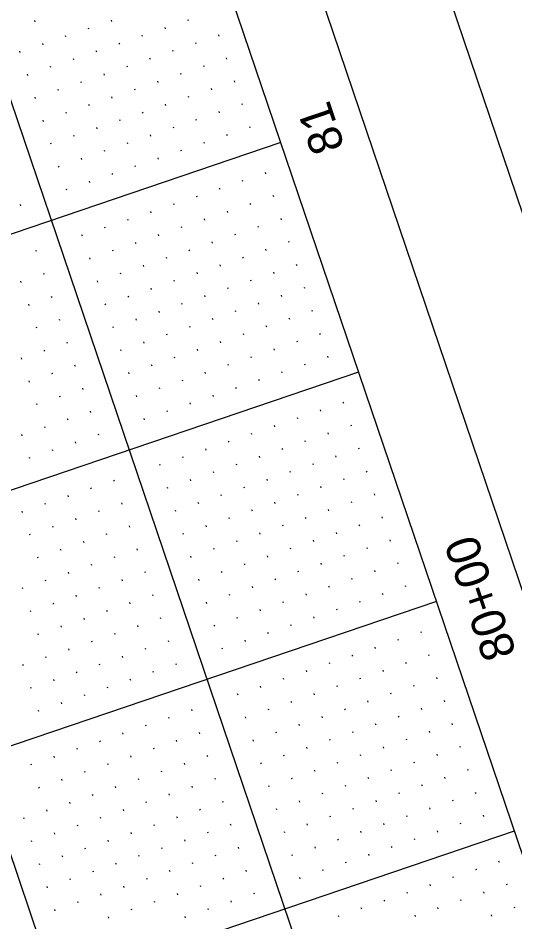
# Model space of a CAD drawing. Extents: x 2150800 to 2152547, y 141860 to 143950.
# Drawn here: x 2152038.2 to 2152140.8, y 143015.3 to 143201.8 of the extents above; entities that cross this region are included whole.
import ezdxf

# ---------------------------------------------------------------- set-up
doc = ezdxf.new("R2010")
doc.units = 0
for name, color, linetype in [('SHT_Plan_Profile_Sheet_Sta_Txt', 7, 'Continuous'), ('SHT_Plot_Shape_Half', 7, 'Continuous'), ('SHT_Profile_Grid_Major', 7, 'Continuous'), ('SHT_Profile_Grid_Minor', 7, 'Continuous'), ('SHT_Sheet_Border', 7, 'Continuous')]:
    doc.layers.add(name, color=color, linetype=linetype)

msp = doc.modelspace()

# ---------------------------------------------------------------- linework, layer by layer
at = {"layer": 'SHT_Plot_Shape_Half'}
msp.add_lwpolyline([(2151391.39, 141950.92), (2150845.24, 143560.8), (2151886.93, 143914.19), (2152433.08, 142304.31)], close=True, dxfattribs=at)
at = {"layer": 'SHT_Profile_Grid_Major'}
for p, q in [((2152314.16, 142366.92), (2151808.17, 143858.43)), ((2152266.81, 142350.86), (2151760.82, 143842.37)), ((2152092.45, 143176.09), (2151618.95, 143015.46)), ((2152092.45, 143176.09), (2151618.96, 143015.46)), ((2152108.51, 143128.74), (2151635.02, 142968.11)), ((2152124.58, 143081.39), (2151651.08, 142920.76)), ((2152140.64, 143034.04), (2151667.15, 142873.41))]:
    msp.add_line(p, q, dxfattribs=at)
at = {"layer": 'SHT_Profile_Grid_Minor'}
for p, q in [((2152041.76, 143201), (2152041.68, 143201.24)), ((2152057.57, 143201.08), (2152057.49, 143201.32)), ((2152073.38, 143201.17), (2152073.3, 143201.4)), ((2152052.84, 143199.48), (2152052.76, 143199.71)), ((2152068.65, 143199.56), (2152068.57, 143199.8)), ((2152048.1, 143197.87), (2152048.02, 143198.11)), ((2152063.91, 143197.96), (2152063.83, 143198.19)), ((2152079.72, 143198.04), (2152079.64, 143198.28)), ((2152043.37, 143196.27), (2152043.29, 143196.5)), ((2152059.18, 143196.35), (2152059.1, 143196.59)), ((2152074.99, 143196.43), (2152074.91, 143196.67)), ((2152038.63, 143194.66), (2152038.55, 143194.9)), ((2152054.44, 143194.74), (2152054.36, 143194.98)), ((2152070.25, 143194.83), (2152070.17, 143195.06)), ((2152049.71, 143193.14), (2152049.63, 143193.37)), ((2152065.52, 143193.22), (2152065.44, 143193.46)), ((2152076.6, 143191.7), (2152076.52, 143191.94)), ((2152081.33, 143193.3), (2152081.25, 143193.54)), ((2152040.24, 143189.92), (2152040.16, 143190.16)), ((2152044.97, 143191.53), (2152044.89, 143191.77)), ((2152056.05, 143190.01), (2152055.97, 143190.24)), ((2152060.78, 143191.61), (2152060.7, 143191.85)), ((2152071.86, 143190.09), (2152071.78, 143190.33)), ((2152051.31, 143188.4), (2152051.23, 143188.64)), ((2152067.13, 143188.49), (2152067.05, 143188.72)), ((2152082.94, 143188.57), (2152082.86, 143188.81)), ((2152046.58, 143186.8), (2152046.5, 143187.03)), ((2152062.39, 143186.88), (2152062.31, 143187.12)), ((2152078.2, 143186.96), (2152078.12, 143187.2)), ((2152041.84, 143185.19), (2152041.76, 143185.43)), ((2152057.66, 143185.27), (2152057.58, 143185.51)), ((2152073.47, 143185.36), (2152073.39, 143185.59)), ((2152052.92, 143183.67), (2152052.84, 143183.9)), ((2152068.73, 143183.75), (2152068.65, 143183.99)), ((2152084.54, 143183.83), (2152084.46, 143184.07)), ((2152048.19, 143182.06), (2152048.11, 143182.3)), ((2152059.26, 143180.54), (2152059.18, 143180.77)), ((2152064, 143182.14), (2152063.92, 143182.38)), ((2152075.07, 143180.62), (2152074.99, 143180.86)), ((2152079.81, 143182.23), (2152079.73, 143182.47)), ((2152043.45, 143180.45), (2152043.37, 143180.69)), ((2152054.53, 143178.93), (2152054.45, 143179.17)), ((2152070.34, 143179.02), (2152070.26, 143179.25)), ((2152086.15, 143179.1), (2152086.07, 143179.34)), ((2152049.79, 143177.33), (2152049.71, 143177.56)), ((2152065.6, 143177.41), (2152065.52, 143177.65)), ((2152081.41, 143177.49), (2152081.33, 143177.73)), ((2152045.06, 143175.72), (2152044.98, 143175.96)), ((2152060.87, 143175.8), (2152060.79, 143176.04)), ((2152076.68, 143175.89), (2152076.6, 143176.12)), ((2152056.13, 143174.2), (2152056.05, 143174.43)), ((2152071.94, 143174.28), (2152071.86, 143174.52)), ((2152051.4, 143172.59), (2152051.32, 143172.83)), ((2152067.21, 143172.67), (2152067.13, 143172.91)), ((2152046.66, 143170.98), (2152046.58, 143171.22)), ((2152057.74, 143169.46), (2152057.66, 143169.7)), ((2152062.47, 143171.07), (2152062.39, 143171.31)), ((2152089.36, 143169.63), (2152089.28, 143169.87)), ((2152053, 143167.86), (2152052.92, 143168.09)), ((2152084.63, 143168.02), (2152084.55, 143168.26)), ((2152048.27, 143166.25), (2152048.19, 143166.49)), ((2152079.89, 143166.42), (2152079.81, 143166.65)), ((2152075.16, 143164.81), (2152075.08, 143165.05)), ((2152090.97, 143164.89), (2152090.89, 143165.13)), ((2152038.8, 143163.04), (2152038.72, 143163.27)), ((2152070.42, 143163.2), (2152070.34, 143163.44)), ((2152086.23, 143163.29), (2152086.15, 143163.53)), ((2152060.95, 143159.99), (2152060.87, 143160.23)), ((2152065.69, 143161.6), (2152065.61, 143161.84)), ((2152076.76, 143160.08), (2152076.68, 143160.31)), ((2152081.5, 143161.68), (2152081.42, 143161.92)), ((2152092.57, 143160.16), (2152092.49, 143160.4)), ((2152056.22, 143158.39), (2152056.14, 143158.62)), ((2152072.03, 143158.47), (2152071.95, 143158.71)), ((2152087.84, 143158.55), (2152087.76, 143158.79)), ((2152051.48, 143156.78), (2152051.4, 143157.02)), ((2152067.29, 143156.86), (2152067.21, 143157.1)), ((2152083.1, 143156.95), (2152083.02, 143157.18)), ((2152062.56, 143155.26), (2152062.48, 143155.49)), ((2152078.37, 143155.34), (2152078.29, 143155.58)), ((2152094.18, 143155.43), (2152094.1, 143155.66)), ((2152042.01, 143153.57), (2152041.93, 143153.8)), ((2152057.82, 143153.65), (2152057.74, 143153.89)), ((2152073.63, 143153.73), (2152073.55, 143153.97)), ((2152089.45, 143153.82), (2152089.37, 143154.06)), ((2152053.09, 143152.04), (2152053.01, 143152.28)), ((2152068.9, 143152.13), (2152068.82, 143152.37)), ((2152084.71, 143152.21), (2152084.63, 143152.45)), ((2152095.79, 143150.69), (2152095.71, 143150.93)), ((2152043.62, 143148.83), (2152043.54, 143149.07)), ((2152059.43, 143148.92), (2152059.35, 143149.15)), ((2152064.17, 143150.52), (2152064.08, 143150.76)), ((2152075.24, 143149), (2152075.16, 143149.24)), ((2152079.98, 143150.61), (2152079.9, 143150.84)), ((2152091.05, 143149.08), (2152090.97, 143149.32)), ((2152038.88, 143147.23), (2152038.8, 143147.46)), ((2152054.7, 143147.31), (2152054.61, 143147.55)), ((2152070.51, 143147.39), (2152070.43, 143147.63)), ((2152086.32, 143147.48), (2152086.24, 143147.71)), ((2152065.77, 143145.79), (2152065.69, 143146.02)), ((2152081.58, 143145.87), (2152081.5, 143146.11)), ((2152097.39, 143145.96), (2152097.31, 143146.19)), ((2152045.23, 143144.1), (2152045.14, 143144.33)), ((2152061.04, 143144.18), (2152060.96, 143144.42)), ((2152076.85, 143144.26), (2152076.77, 143144.5)), ((2152092.66, 143144.35), (2152092.58, 143144.59)), ((2152040.49, 143142.49), (2152040.41, 143142.73)), ((2152056.3, 143142.57), (2152056.22, 143142.81)), ((2152072.11, 143142.66), (2152072.03, 143142.9)), ((2152087.92, 143142.74), (2152087.84, 143142.98)), ((2152067.38, 143141.05), (2152067.3, 143141.29)), ((2152078.45, 143139.53), (2152078.37, 143139.77)), ((2152083.19, 143141.14), (2152083.11, 143141.37)), ((2152094.27, 143139.61), (2152094.18, 143139.85)), ((2152099, 143141.22), (2152098.92, 143141.46)), ((2152042.1, 143137.76), (2152042.02, 143137.99)), ((2152046.83, 143139.36), (2152046.75, 143139.6)), ((2152057.91, 143137.84), (2152057.83, 143138.08)), ((2152062.64, 143139.45), (2152062.56, 143139.68)), ((2152073.72, 143137.92), (2152073.64, 143138.16)), ((2152089.53, 143138.01), (2152089.45, 143138.24)), ((2152068.98, 143136.32), (2152068.9, 143136.55)), ((2152084.8, 143136.4), (2152084.71, 143136.64)), ((2152100.61, 143136.49), (2152100.53, 143136.72)), ((2152048.44, 143134.63), (2152048.36, 143134.86)), ((2152064.25, 143134.71), (2152064.17, 143134.95)), ((2152080.06, 143134.79), (2152079.98, 143135.03)), ((2152095.87, 143134.88), (2152095.79, 143135.12)), ((2152043.7, 143133.02), (2152043.62, 143133.26)), ((2152059.51, 143133.1), (2152059.43, 143133.34)), ((2152075.33, 143133.19), (2152075.24, 143133.43)), ((2152091.14, 143133.27), (2152091.06, 143133.51)), ((2152038.97, 143131.41), (2152038.89, 143131.65)), ((2152070.59, 143131.58), (2152070.51, 143131.82)), ((2152086.4, 143131.67), (2152086.32, 143131.9)), ((2152097.48, 143130.14), (2152097.4, 143130.38)), ((2152102.21, 143131.75), (2152102.13, 143131.99)), ((2152045.31, 143128.29), (2152045.23, 143128.52)), ((2152050.04, 143129.89), (2152049.96, 143130.13)), ((2152061.12, 143128.37), (2152061.04, 143128.61)), ((2152065.86, 143129.98), (2152065.78, 143130.21)), ((2152076.93, 143128.45), (2152076.85, 143128.69)), ((2152081.67, 143130.06), (2152081.59, 143130.3)), ((2152092.74, 143128.54), (2152092.66, 143128.77)), ((2152040.57, 143126.68), (2152040.49, 143126.92)), ((2152072.2, 143126.85), (2152072.12, 143127.08)), ((2152088.01, 143126.93), (2152087.93, 143127.17)), ((2152051.65, 143125.16), (2152051.57, 143125.39)), ((2152067.46, 143125.24), (2152067.38, 143125.48)), ((2152083.27, 143125.33), (2152083.19, 143125.56)), ((2152046.92, 143123.55), (2152046.84, 143123.79)), ((2152062.73, 143123.63), (2152062.65, 143123.87)), ((2152078.54, 143123.72), (2152078.46, 143123.96)), ((2152042.18, 143121.94), (2152042.1, 143122.18)), ((2152073.8, 143122.11), (2152073.72, 143122.35)), ((2152105.43, 143122.28), (2152105.34, 143122.52)), ((2152053.26, 143120.42), (2152053.18, 143120.66)), ((2152069.07, 143120.51), (2152068.99, 143120.74)), ((2152095.96, 143119.07), (2152095.88, 143119.3)), ((2152100.69, 143120.67), (2152100.61, 143120.91)), ((2152043.79, 143117.21), (2152043.71, 143117.45)), ((2152048.52, 143118.82), (2152048.44, 143119.05)), ((2152064.33, 143118.9), (2152064.25, 143119.14)), ((2152091.22, 143117.46), (2152091.14, 143117.7)), ((2152107.03, 143117.55), (2152106.95, 143117.78)), ((2152039.05, 143115.6), (2152038.97, 143115.84)), ((2152054.86, 143115.69), (2152054.78, 143115.92)), ((2152086.49, 143115.86), (2152086.41, 143116.09)), ((2152102.3, 143115.94), (2152102.22, 143116.18)), ((2152050.13, 143114.08), (2152050.05, 143114.32)), ((2152081.75, 143114.25), (2152081.67, 143114.49)), ((2152097.56, 143114.33), (2152097.48, 143114.57)), ((2152045.39, 143112.47), (2152045.31, 143112.71)), ((2152077.02, 143112.64), (2152076.94, 143112.88)), ((2152092.83, 143112.73), (2152092.75, 143112.96)), ((2152108.64, 143112.81), (2152108.56, 143113.05)), ((2152040.66, 143110.87), (2152040.58, 143111.1)), ((2152072.28, 143111.04), (2152072.2, 143111.27)), ((2152088.09, 143111.12), (2152088.01, 143111.36)), ((2152103.9, 143111.2), (2152103.82, 143111.44)), ((2152067.55, 143109.43), (2152067.47, 143109.67)), ((2152078.62, 143107.91), (2152078.54, 143108.14)), ((2152083.36, 143109.51), (2152083.28, 143109.75)), ((2152094.43, 143107.99), (2152094.35, 143108.23)), ((2152099.17, 143109.6), (2152099.09, 143109.83)), ((2152110.24, 143108.08), (2152110.16, 143108.31)), ((2152058.08, 143106.22), (2152058, 143106.45)), ((2152073.89, 143106.3), (2152073.81, 143106.54)), ((2152089.7, 143106.39), (2152089.62, 143106.62)), ((2152105.51, 143106.47), (2152105.43, 143106.71)), ((2152053.34, 143104.61), (2152053.26, 143104.85)), ((2152069.15, 143104.69), (2152069.07, 143104.93)), ((2152084.96, 143104.78), (2152084.88, 143105.02)), ((2152100.77, 143104.86), (2152100.69, 143105.1)), ((2152048.61, 143103), (2152048.53, 143103.24)), ((2152080.23, 143103.17), (2152080.15, 143103.41)), ((2152096.04, 143103.26), (2152095.96, 143103.49)), ((2152111.85, 143103.34), (2152111.77, 143103.58)), ((2152043.87, 143101.4), (2152043.79, 143101.64)), ((2152059.68, 143101.48), (2152059.6, 143101.72)), ((2152075.49, 143101.57), (2152075.41, 143101.8)), ((2152091.3, 143101.65), (2152091.22, 143101.89)), ((2152107.12, 143101.73), (2152107.04, 143101.97)), ((2152039.14, 143099.79), (2152039.06, 143100.03)), ((2152054.95, 143099.88), (2152054.87, 143100.11)), ((2152070.76, 143099.96), (2152070.68, 143100.2)), ((2152081.83, 143098.44), (2152081.75, 143098.67)), ((2152086.57, 143100.04), (2152086.49, 143100.28)), ((2152097.65, 143098.52), (2152097.57, 143098.76)), ((2152102.38, 143100.13), (2152102.3, 143100.36)), ((2152113.46, 143098.61), (2152113.38, 143098.84)), ((2152045.48, 143096.66), (2152045.4, 143096.9)), ((2152050.21, 143098.27), (2152050.13, 143098.51)), ((2152061.29, 143096.75), (2152061.21, 143096.98)), ((2152077.1, 143096.83), (2152077.02, 143097.07)), ((2152092.91, 143096.92), (2152092.83, 143097.15)), ((2152108.72, 143097), (2152108.64, 143097.24)), ((2152040.74, 143095.06), (2152040.66, 143095.29)), ((2152056.55, 143095.14), (2152056.47, 143095.38)), ((2152072.36, 143095.23), (2152072.28, 143095.46)), ((2152088.18, 143095.31), (2152088.1, 143095.55)), ((2152103.99, 143095.39), (2152103.91, 143095.63)), ((2152051.82, 143093.53), (2152051.74, 143093.77)), ((2152083.44, 143093.7), (2152083.36, 143093.94)), ((2152099.25, 143093.79), (2152099.17, 143094.02)), ((2152115.06, 143093.87), (2152114.98, 143094.11)), ((2152047.08, 143091.93), (2152047, 143092.17)), ((2152062.89, 143092.01), (2152062.81, 143092.25)), ((2152078.71, 143092.1), (2152078.63, 143092.33)), ((2152094.52, 143092.18), (2152094.44, 143092.42)), ((2152110.33, 143092.26), (2152110.25, 143092.5)), ((2152042.35, 143090.32), (2152042.27, 143090.56)), ((2152058.16, 143090.41), (2152058.08, 143090.64)), ((2152073.97, 143090.49), (2152073.89, 143090.73)), ((2152089.78, 143090.57), (2152089.7, 143090.81)), ((2152105.59, 143090.66), (2152105.51, 143090.89)), ((2152116.67, 143089.14), (2152116.59, 143089.37)), ((2152053.42, 143088.8), (2152053.34, 143089.04)), ((2152064.5, 143087.28), (2152064.42, 143087.51)), ((2152080.31, 143087.36), (2152080.23, 143087.6)), ((2152085.05, 143088.97), (2152084.97, 143089.2)), ((2152096.12, 143087.45), (2152096.04, 143087.68)), ((2152100.86, 143089.05), (2152100.78, 143089.29)), ((2152111.93, 143087.53), (2152111.85, 143087.77)), ((2152043.95, 143085.59), (2152043.87, 143085.82)), ((2152048.69, 143087.19), (2152048.61, 143087.43)), ((2152059.77, 143085.67), (2152059.69, 143085.91)), ((2152075.58, 143085.76), (2152075.5, 143085.99)), ((2152091.39, 143085.84), (2152091.31, 143086.08)), ((2152107.2, 143085.92), (2152107.12, 143086.16)), ((2152039.22, 143083.98), (2152039.14, 143084.22)), ((2152055.03, 143084.06), (2152054.95, 143084.3)), ((2152086.65, 143084.23), (2152086.57, 143084.47)), ((2152102.46, 143084.32), (2152102.38, 143084.55)), ((2152118.28, 143084.4), (2152118.2, 143084.64)), ((2152050.3, 143082.46), (2152050.22, 143082.7)), ((2152066.11, 143082.54), (2152066.03, 143082.78)), ((2152081.92, 143082.63), (2152081.84, 143082.86)), ((2152097.73, 143082.71), (2152097.65, 143082.95)), ((2152113.54, 143082.79), (2152113.46, 143083.03)), ((2152045.56, 143080.85), (2152045.48, 143081.09)), ((2152061.37, 143080.94), (2152061.29, 143081.17)), ((2152077.18, 143081.02), (2152077.1, 143081.26)), ((2152092.99, 143081.1), (2152092.91, 143081.34)), ((2152108.81, 143081.19), (2152108.73, 143081.42)), ((2152040.83, 143079.25), (2152040.75, 143079.48)), ((2152056.64, 143079.33), (2152056.56, 143079.57)), ((2152088.26, 143079.5), (2152088.18, 143079.73)), ((2152099.34, 143077.98), (2152099.26, 143078.21)), ((2152104.07, 143079.58), (2152103.99, 143079.82)), ((2152047.17, 143076.12), (2152047.09, 143076.35)), ((2152051.9, 143077.72), (2152051.82, 143077.96)), ((2152062.98, 143076.2), (2152062.9, 143076.44)), ((2152067.71, 143077.81), (2152067.63, 143078.04)), ((2152078.79, 143076.29), (2152078.71, 143076.52)), ((2152083.52, 143077.89), (2152083.44, 143078.13)), ((2152094.6, 143076.37), (2152094.52, 143076.61)), ((2152042.43, 143074.51), (2152042.35, 143074.75)), ((2152058.24, 143074.59), (2152058.16, 143074.83)), ((2152089.87, 143074.76), (2152089.79, 143075)), ((2152121.49, 143074.93), (2152121.41, 143075.17)), ((2152053.51, 143072.99), (2152053.43, 143073.23)), ((2152069.32, 143073.07), (2152069.24, 143073.31)), ((2152085.13, 143073.16), (2152085.05, 143073.39)), ((2152116.75, 143073.32), (2152116.67, 143073.56)), ((2152048.77, 143071.38), (2152048.69, 143071.62)), ((2152064.58, 143071.47), (2152064.5, 143071.7)), ((2152080.4, 143071.55), (2152080.32, 143071.79)), ((2152112.02, 143071.72), (2152111.94, 143071.95)), ((2152044.04, 143069.78), (2152043.96, 143070.01)), ((2152059.85, 143069.86), (2152059.77, 143070.1)), ((2152107.28, 143070.11), (2152107.2, 143070.35)), ((2152123.09, 143070.2), (2152123.01, 143070.43)), ((2152039.3, 143068.17), (2152039.22, 143068.41)), ((2152055.12, 143068.25), (2152055.03, 143068.49)), ((2152066.19, 143066.73), (2152066.11, 143066.97)), ((2152070.93, 143068.34), (2152070.85, 143068.57)), ((2152097.81, 143066.9), (2152097.73, 143067.14)), ((2152102.55, 143068.51), (2152102.47, 143068.74)), ((2152113.62, 143066.98), (2152113.54, 143067.22)), ((2152118.36, 143068.59), (2152118.28, 143068.83)), ((2152045.65, 143065.04), (2152045.56, 143065.28)), ((2152050.38, 143066.65), (2152050.3, 143066.88)), ((2152061.46, 143065.13), (2152061.38, 143065.36)), ((2152093.08, 143065.29), (2152093, 143065.53)), ((2152108.89, 143065.38), (2152108.81, 143065.61)), ((2152124.7, 143065.46), (2152124.62, 143065.7)), ((2152040.91, 143063.43), (2152040.83, 143063.67)), ((2152056.72, 143063.52), (2152056.64, 143063.76)), ((2152088.34, 143063.69), (2152088.26, 143063.92)), ((2152104.15, 143063.77), (2152104.07, 143064.01)), ((2152119.97, 143063.85), (2152119.89, 143064.09)), ((2152051.99, 143061.91), (2152051.91, 143062.15)), ((2152083.61, 143062.08), (2152083.53, 143062.32)), ((2152099.42, 143062.16), (2152099.34, 143062.4)), ((2152115.23, 143062.25), (2152115.15, 143062.49)), ((2152047.25, 143060.31), (2152047.17, 143060.54)), ((2152094.69, 143060.56), (2152094.6, 143060.79)), ((2152110.5, 143060.64), (2152110.42, 143060.88)), ((2152126.31, 143060.73), (2152126.23, 143060.96)), ((2152042.52, 143058.7), (2152042.44, 143058.94)), ((2152074.14, 143058.87), (2152074.06, 143059.1)), ((2152089.95, 143058.95), (2152089.87, 143059.19)), ((2152101.03, 143057.43), (2152100.95, 143057.67)), ((2152105.76, 143059.04), (2152105.68, 143059.27)), ((2152116.84, 143057.51), (2152116.76, 143057.75)), ((2152121.57, 143059.12), (2152121.49, 143059.36)), ((2152064.67, 143055.66), (2152064.59, 143055.89)), ((2152069.4, 143057.26), (2152069.32, 143057.5)), ((2152085.22, 143057.35), (2152085.13, 143057.58)), ((2152096.29, 143055.82), (2152096.21, 143056.06)), ((2152112.1, 143055.91), (2152112.02, 143056.14)), ((2152127.91, 143055.99), (2152127.83, 143056.23)), ((2152059.93, 143054.05), (2152059.85, 143054.29)), ((2152075.75, 143054.13), (2152075.66, 143054.37)), ((2152091.56, 143054.22), (2152091.48, 143054.45)), ((2152107.37, 143054.3), (2152107.29, 143054.54)), ((2152123.18, 143054.38), (2152123.1, 143054.62)), ((2152055.2, 143052.44), (2152055.12, 143052.68)), ((2152071.01, 143052.53), (2152070.93, 143052.76)), ((2152086.82, 143052.61), (2152086.74, 143052.85)), ((2152102.63, 143052.69), (2152102.55, 143052.93)), ((2152118.44, 143052.78), (2152118.36, 143053.02)), ((2152050.46, 143050.84), (2152050.38, 143051.07)), ((2152066.28, 143050.92), (2152066.2, 143051.16)), ((2152097.9, 143051.09), (2152097.82, 143051.32)), ((2152113.71, 143051.17), (2152113.63, 143051.41)), ((2152129.52, 143051.26), (2152129.44, 143051.49)), ((2152045.73, 143049.23), (2152045.65, 143049.47)), ((2152061.54, 143049.31), (2152061.46, 143049.55)), ((2152077.35, 143049.4), (2152077.27, 143049.63)), ((2152093.16, 143049.48), (2152093.08, 143049.72)), ((2152108.97, 143049.57), (2152108.89, 143049.8)), ((2152124.79, 143049.65), (2152124.7, 143049.89)), ((2152040.99, 143047.62), (2152040.91, 143047.86)), ((2152056.81, 143047.71), (2152056.73, 143047.94)), ((2152072.62, 143047.79), (2152072.54, 143048.03)), ((2152088.43, 143047.88), (2152088.35, 143048.11)), ((2152099.5, 143046.35), (2152099.42, 143046.59)), ((2152104.24, 143047.96), (2152104.16, 143048.2)), ((2152115.32, 143046.44), (2152115.23, 143046.67)), ((2152120.05, 143048.04), (2152119.97, 143048.28)), ((2152131.13, 143046.52), (2152131.05, 143046.76)), ((2152047.34, 143044.49), (2152047.26, 143044.73)), ((2152052.07, 143046.1), (2152051.99, 143046.34)), ((2152063.15, 143044.58), (2152063.07, 143044.82)), ((2152067.88, 143046.19), (2152067.8, 143046.42)), ((2152078.96, 143044.66), (2152078.88, 143044.9)), ((2152094.77, 143044.75), (2152094.69, 143044.98)), ((2152110.58, 143044.83), (2152110.5, 143045.07)), ((2152126.39, 143044.91), (2152126.31, 143045.15)), ((2152042.6, 143042.89), (2152042.52, 143043.13)), ((2152058.41, 143042.97), (2152058.33, 143043.21)), ((2152074.22, 143043.06), (2152074.14, 143043.29)), ((2152090.03, 143043.14), (2152089.95, 143043.38)), ((2152105.85, 143043.22), (2152105.76, 143043.46)), ((2152121.66, 143043.31), (2152121.58, 143043.55)), ((2152053.68, 143041.37), (2152053.6, 143041.6)), ((2152069.49, 143041.45), (2152069.41, 143041.69)), ((2152101.11, 143041.62), (2152101.03, 143041.86)), ((2152116.92, 143041.7), (2152116.84, 143041.94)), ((2152132.73, 143041.79), (2152132.65, 143042.02)), ((2152048.94, 143039.76), (2152048.86, 143040)), ((2152064.75, 143039.84), (2152064.67, 143040.08)), ((2152080.56, 143039.93), (2152080.48, 143040.16)), ((2152096.38, 143040.01), (2152096.3, 143040.25)), ((2152112.19, 143040.1), (2152112.11, 143040.33)), ((2152128, 143040.18), (2152127.92, 143040.42)), ((2152044.21, 143038.15), (2152044.13, 143038.39)), ((2152060.02, 143038.24), (2152059.94, 143038.47)), ((2152075.83, 143038.32), (2152075.75, 143038.56)), ((2152091.64, 143038.41), (2152091.56, 143038.64)), ((2152107.45, 143038.49), (2152107.37, 143038.73)), ((2152118.53, 143036.97), (2152118.45, 143037.2)), ((2152123.26, 143038.57), (2152123.18, 143038.81)), ((2152134.34, 143037.05), (2152134.26, 143037.29)), ((2152039.47, 143036.55), (2152039.39, 143036.78)), ((2152055.28, 143036.63), (2152055.2, 143036.87)), ((2152066.36, 143035.11), (2152066.28, 143035.35)), ((2152071.09, 143036.72), (2152071.01, 143036.95)), ((2152082.17, 143035.19), (2152082.09, 143035.43)), ((2152097.98, 143035.28), (2152097.9, 143035.51)), ((2152102.72, 143036.88), (2152102.64, 143037.12)), ((2152113.79, 143035.36), (2152113.71, 143035.6)), ((2152129.6, 143035.45), (2152129.52, 143035.68)), ((2152045.81, 143033.42), (2152045.73, 143033.66)), ((2152050.55, 143035.03), (2152050.47, 143035.26)), ((2152061.62, 143033.5), (2152061.54, 143033.74)), ((2152077.44, 143033.59), (2152077.36, 143033.82)), ((2152093.25, 143033.67), (2152093.17, 143033.91)), ((2152109.06, 143033.75), (2152108.98, 143033.99)), ((2152124.87, 143033.84), (2152124.79, 143034.08)), ((2152041.08, 143031.81), (2152041, 143032.05)), ((2152056.89, 143031.9), (2152056.81, 143032.13)), ((2152072.7, 143031.98), (2152072.62, 143032.22)), ((2152104.32, 143032.15), (2152104.24, 143032.39)), ((2152120.13, 143032.23), (2152120.05, 143032.47)), ((2152052.15, 143030.29), (2152052.07, 143030.53)), ((2152067.97, 143030.37), (2152067.89, 143030.61)), ((2152083.78, 143030.46), (2152083.7, 143030.69)), ((2152099.59, 143030.54), (2152099.51, 143030.78)), ((2152115.4, 143030.63), (2152115.32, 143030.86)), ((2152047.42, 143028.68), (2152047.34, 143028.92)), ((2152063.23, 143028.77), (2152063.15, 143029)), ((2152079.04, 143028.85), (2152078.96, 143029.09)), ((2152094.85, 143028.94), (2152094.77, 143029.17)), ((2152110.66, 143029.02), (2152110.58, 143029.26)), ((2152137.55, 143027.58), (2152137.47, 143027.82)), ((2152042.68, 143027.08), (2152042.6, 143027.31)), ((2152058.5, 143027.16), (2152058.42, 143027.4)), ((2152074.31, 143027.25), (2152074.23, 143027.48)), ((2152085.38, 143025.72), (2152085.3, 143025.96)), ((2152101.19, 143025.81), (2152101.11, 143026.04)), ((2152105.93, 143027.41), (2152105.85, 143027.65)), ((2152132.82, 143025.98), (2152132.74, 143026.21)), ((2152049.03, 143023.95), (2152048.95, 143024.19)), ((2152053.76, 143025.56), (2152053.68, 143025.79)), ((2152064.84, 143024.03), (2152064.76, 143024.27)), ((2152069.57, 143025.64), (2152069.49, 143025.88)), ((2152080.65, 143024.12), (2152080.57, 143024.35)), ((2152096.46, 143024.2), (2152096.38, 143024.44)), ((2152128.08, 143024.37), (2152128, 143024.61)), ((2152044.29, 143022.34), (2152044.21, 143022.58)), ((2152060.1, 143022.43), (2152060.02, 143022.66)), ((2152075.91, 143022.51), (2152075.83, 143022.75)), ((2152123.35, 143022.76), (2152123.27, 143023)), ((2152139.16, 143022.85), (2152139.08, 143023.08)), ((2152055.37, 143020.82), (2152055.29, 143021.06)), ((2152071.18, 143020.9), (2152071.1, 143021.14)), ((2152086.99, 143020.99), (2152086.91, 143021.22)), ((2152118.61, 143021.16), (2152118.53, 143021.39)), ((2152134.42, 143021.24), (2152134.34, 143021.48)), ((2152050.63, 143019.21), (2152050.55, 143019.45)), ((2152066.44, 143019.3), (2152066.36, 143019.53)), ((2152082.25, 143019.38), (2152082.17, 143019.62)), ((2152113.88, 143019.55), (2152113.8, 143019.79)), ((2152129.69, 143019.63), (2152129.61, 143019.87)), ((2152045.9, 143017.61), (2152045.82, 143017.84)), ((2152061.71, 143017.69), (2152061.63, 143017.93)), ((2152077.52, 143017.78), (2152077.44, 143018.01)), ((2152109.14, 143017.94), (2152109.06, 143018.18)), ((2152120.22, 143016.42), (2152120.14, 143016.66)), ((2152124.95, 143018.03), (2152124.87, 143018.26)), ((2152136.03, 143016.51), (2152135.95, 143016.74)), ((2152140.76, 143018.11), (2152140.68, 143018.35)), ((2152056.97, 143016.09), (2152056.89, 143016.32)), ((2152072.78, 143016.17), (2152072.7, 143016.41)), ((2152104.41, 143016.34), (2152104.33, 143016.57))]:
    msp.add_line(p, q, dxfattribs=at)
at = {"layer": 'SHT_Sheet_Border'}
msp.add_line((2152361.51, 142382.99), (2151939.85, 143625.91), dxfattribs=at)
msp.add_lwpolyline([(2151383.74, 142051.28), (2150877.75, 143542.79), (2151872.09, 143880.12), (2152378.08, 142388.61)], close=True, dxfattribs=at)

# ---------------------------------------------------------------- texts
at = {"layer": 'SHT_Plan_Profile_Sheet_Sta_Txt'}
for s, p in [('81', (2152105.7, 143175.16)), ('80+00', (2152141.14, 143070.69))]:
    msp.add_text(s, height=7, rotation=108.7393, dxfattribs=at).set_placement(p)

doc.saveas('drawing.dxf')
